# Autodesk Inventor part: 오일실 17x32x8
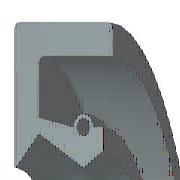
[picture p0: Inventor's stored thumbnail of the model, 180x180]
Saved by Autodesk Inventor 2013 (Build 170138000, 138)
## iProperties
IsCustomPart: 1
Created: 2009-02
Part Number: 오일실 17x32x8
Material: 고무
Description: 오일-실
Document SubType Name: Modeling
Standard: KS B 2804
Designer: 한국산업디자인학원
Standards Organization: KS
Language: ko-KR
Size Designation: D - 17 32 8
Categories: <MemberInstance><Categories><Category DisplayName="샤프트 부품" InternalName="7f7aeb1f-a693-4053-b835-cee3144e0d98" Mnemonic="SHFT"><Category DisplayName="실링" Intern
Density: 0.93 g/cm^3
Author: 한국산업디자인학원
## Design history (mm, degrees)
revolve "본체" stored, may be unused: angle "d17" = 90 deg
revolve "스프링1" stored, may be unused: angle "d18" = 90 deg
body "Solid1"
sketch "스케치1"
  geometry: L1 (0, 16)-(8, 16); L2 (8, 14.25)-(1.75, 14.25); L3 (1.75, 10.25)-(4.9, 8.5); L4 (4.9, 8.5)-(0, 8.5); L5 (0, 0)-(9.586, 0) reference; L6 (4.9, 8.5)-(6.3, 9.375); L7 (0, 18)-(0, -3) reference; L8 (-1.941, 0)-(11.507, 0) reference; L9 (4.2, 10.6)-(1.75, 11.21); L10 (1.75, 11.21)-(1.75, 14.25); L11 (0, 16)-(0, 8.588); L12 (4.9, 8.5)-(0, 8.5); L13 (1.75, 10.25)-(0.152, 8.528); L14 (8, 16)-(8, 14.25); L15 (5.6, 10.6)-(6.3, 10.6); L16 (6.3, 10.6)-(6.3, 9.375); C1 r 0.455 at (4.9, 10.6); A1 r 0.7 centre (4.9, 10.6) between (5.6, 10.6) and (4.2, 10.6); A2 r 0.088 centre (0.088, 8.588) between (0, 8.588) and (0.152, 8.528); 1 further point
  constraints: 28 end point, 5 horizontal alignment, 5 point on line, 4 point on circle, 4 vertical alignment, 3 centre point, 3 tangent, 2 collinear, 2 horizontal, 2 perpendicular, 1 coincident, 1 parallel
  dimensions: "d0" = 32 diameter of L1 L5 (= SD2); "d1" = 1.75 distance of L1.end L2.start (= SD); "d2" = 0.91 diameter of C1 (= SPDI); "d3" = 1.4 diameter of A1 (= SPDA); "d4" = 17 diameter of L3.end L5 (= NND); "d5" = 20.5 diameter of L3.start L5 (= TKDM); "d7" = 22.42 diameter of L9.end L5 (= TKDM + 0.24 x SWDT); "d8" = 1.75 distance between parallel lines of L11 L10 (= SD); "d9" = 4.9 distance from line of L11 C1.centre (= SPDST); "d10" = 21.2 diameter of C1.centre L5 (= HLDM); "d11" = 0.0875 radius of A2 (= 0.25 x LAB); "d12" = 6.3 distance between parallel lines of L11 L16 (= SDI); "d13" = 18.75 diameter of L6.end L5 (= ABDM); "d14" = 8 distance from line of L11 L1.end (= SWDT)
fillet "모깎기1" dims "d6" = 0.3 (= RR)
other parameters: "SD2" = 32 [user parameter; used in 1 equation term], "SWDT" = 8 [user parameter; used in 2 equation terms], "RR" = 0.3 [user parameter; used in 1 equation term], "SD" = 1.75 [user parameter; used in 2 equation terms], "NND" = 17 [user parameter; used in 1 equation term], "SPDA" = 1.4 [user parameter; used in 1 equation term], "SPDI" = 0.91 [user parameter; used in 1 equation term], "TKDM" = 20.5 [user parameter; used in 2 equation terms], "HLDM" = 21.2 [user parameter; used in 1 equation term], "ABDM" = 18.75 [user parameter; used in 1 equation term], "SDI" = 6.3 [user parameter; used in 1 equation term], "SPDST" = 4.9 [user parameter; used in 1 equation term], "LAB" = 0.35 [user parameter; used in 1 equation term], "d15" = 0, "d16" = 0, "d19" = 0
